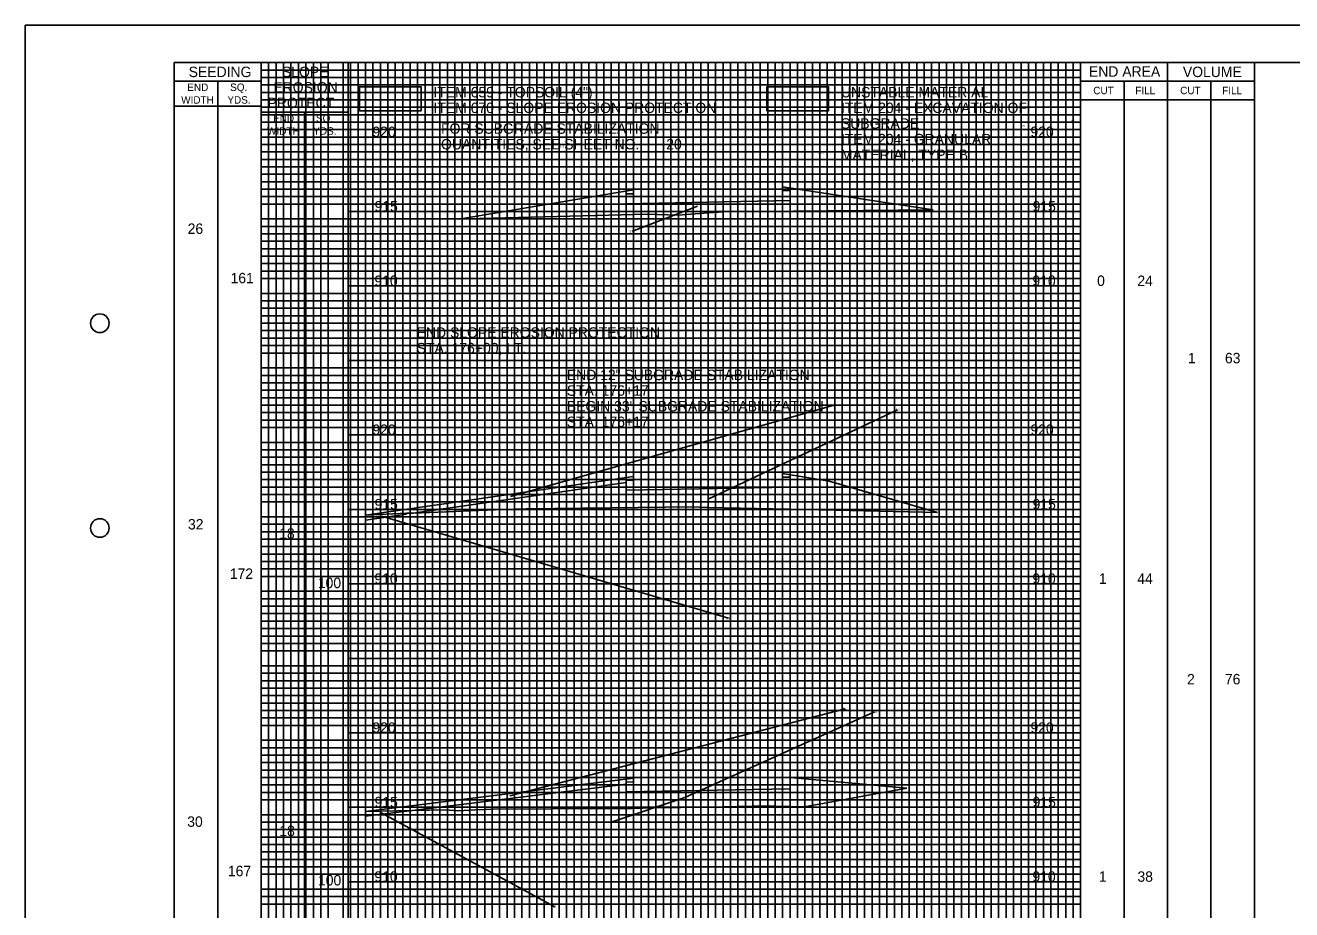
# Model space of a CAD drawing. Extents: x -73 to 160, y -2 to 1877.
# Drawn here: x -10 to 75, y 738.1 to 797.5 of the extents above; entities that cross this region are included whole.
import ezdxf

# ---------------------------------------------------------------- set-up
doc = ezdxf.new("R2010")
doc.units = 0
for name, color, linetype in [('DR_P_Flood_Boundary', 7, 'Continuous'), ('GK_Cells', 7, 'Continuous'), ('PV_P_Drive', 7, 'Continuous'), ('PV_P_EOP', 7, 'Continuous'), ('RD_X_Fence', 7, 'Continuous'), ('TX_X_5', 7, 'Continuous'), ('UT_P_Water_Cells', 7, 'Continuous'), ('XS_P_Pavt_Surface', 7, 'Continuous'), ('XS_P_Special_Benching', 7, 'Continuous'), ('XS_X_Ground_Line', 7, 'Continuous')]:
    doc.layers.add(name, color=color, linetype=linetype)

msp = doc.modelspace()

# ---------------------------------------------------------------- linework, layer by layer
at = {"layer": 'DR_P_Flood_Boundary'}
for p, q in [((15.832, 690), (15.832, 795)), ((20.832, 690), (20.832, 795)), ((25.832, 690), (25.832, 795)), ((30.832, 690), (30.832, 795)), ((35.832, 690), (35.832, 795)), ((40.832, 690), (40.832, 795)), ((45.832, 690), (45.832, 795)), ((50.832, 690), (50.832, 795)), ((55.832, 690), (55.832, 795)), ((5.832, 790), (60.832, 790)), ((11.665, 785), (60.832, 785)), ((11.665, 780), (60.832, 780)), ((11.665, 775), (60.832, 775)), ((11.665, 770), (60.832, 770)), ((11.665, 765), (60.832, 765)), ((11.665, 760), (60.832, 760)), ((11.665, 755), (60.832, 755)), ((11.665, 750), (60.832, 750)), ((11.665, 745), (60.832, 745)), ((11.665, 740), (60.832, 740))]:
    msp.add_line(p, q, dxfattribs=at)
at = {"layer": 'GK_Cells'}
msp.add_lwpolyline([(0, 795), (157.5, 795), (157.5, 690), (0, 690)], close=True, dxfattribs=at)
for centre in [(-5, 777.5), (-5, 763.75)]:
    msp.add_circle(centre, 0.625, dxfattribs=at)
at = {"layer": 'PV_P_Drive'}
msp.add_lwpolyline([(12.427, 793.375), (16.568, 793.375), (16.568, 791.76), (12.427, 791.76)], close=True, dxfattribs=at)
msp.add_lwpolyline([(12.427, 791.76), (16.568, 791.76), (16.568, 793.375), (12.427, 793.375), (12.427, 791.76)], dxfattribs=at)
at = {"layer": 'PV_P_EOP'}
msp.add_lwpolyline([(39.777, 793.375), (43.917, 793.375), (43.917, 791.76), (39.777, 791.76)], close=True, dxfattribs=at)
msp.add_lwpolyline([(39.777, 791.76), (43.917, 791.76), (43.917, 793.375), (39.777, 793.375), (39.777, 791.76)], dxfattribs=at)
at = {"layer": 'RD_X_Fence'}
for p, q in [((30.832, 786.447), (19.095, 784.49)), ((50.943, 785.106), (40.832, 786.647)), ((40.832, 786.397), (41.332, 786.407)), ((41.332, 786.407), (41.332, 785.74)), ((30.332, 786.187), (30.832, 786.197)), ((30.332, 785.52), (30.332, 786.187)), ((41.332, 785.74), (30.332, 785.52)), ((35.107, 785.349), (30.759, 783.677)), ((22.573, 765.857), (44.2, 771.986)), ((35.873, 765.714), (48.535, 771.688)), ((30.832, 767.21), (12.833, 764.607)), ((30.332, 766.808), (16.041, 764.741)), ((16.041, 764.741), (30.332, 766.808)), ((30.332, 766.95), (30.832, 766.96)), ((30.332, 766.808), (30.332, 766.95)), ((30.332, 766.283), (30.332, 766.808)), ((30.832, 767.106), (30.832, 767.21)), ((30.832, 766.96), (30.832, 767.106)), ((43.956, 766.889), (40.832, 767.41)), ((40.832, 767.16), (41.332, 767.17)), ((41.332, 767.17), (41.332, 766.503)), ((51.237, 764.788), (43.956, 766.889)), ((41.332, 766.503), (30.332, 766.283)), ((35.832, 765.135), (42.332, 764.988)), ((15.585, 764.742), (12.833, 764.607)), ((12.833, 764.277), (15.595, 764.676)), ((12.833, 764.607), (12.833, 764.277)), ((13.906, 764.546), (37.188, 757.697)), ((42.332, 764.988), (51.237, 764.788)), ((22.514, 745.765), (45.027, 751.613)), ((34.266, 745.651), (46.992, 751.4)), ((30.832, 746.955), (12.833, 744.724)), ((30.332, 746.563), (15.982, 744.784)), ((15.982, 744.784), (30.332, 746.563)), ((30.332, 746.563), (30.332, 746.695)), ((30.332, 746.028), (30.332, 746.563)), ((30.832, 746.851), (30.832, 746.955)), ((30.832, 746.709), (30.832, 746.851)), ((41.332, 746.915), (41.332, 746.248)), ((49.173, 746.293), (41.341, 747.005)), ((34.397, 745.692), (29.453, 744.046)), ((41.332, 746.248), (30.332, 746.028)), ((42.303, 745.034), (49.173, 746.293)), ((12.833, 744.394), (15.982, 744.784)), ((15.982, 744.784), (12.833, 744.724)), ((12.833, 744.724), (15.982, 744.784)), ((12.833, 744.724), (12.833, 744.394)), ((13.882, 744.634), (25.532, 738.324)), ((29.332, 744.919), (30.687, 744.926)), ((30.687, 744.926), (32.177, 744.953)), ((32.177, 744.953), (35.833, 745.018)), ((35.833, 745.018), (38.881, 745.073)), ((38.881, 745.073), (40.306, 745.085)), ((40.306, 745.085), (42.303, 745.034))]:
    msp.add_line(p, q, dxfattribs=at)
for points in [[(30.832, 786.197), (30.832, 786.342), (30.832, 786.447)], [(40.832, 786.647), (40.832, 786.542), (40.832, 786.397)], [(19.095, 784.49), (20.479, 784.529), (31.739, 784.832), (33.798, 784.764), (35.832, 784.912), (36.891, 784.989), (50.943, 785.106)], [(40.832, 767.41), (40.832, 767.306), (40.832, 767.16)], [(16.041, 764.741), (22.09, 764.99), (23.611, 765.028), (29.332, 765.108), (32.952, 765.159), (34.328, 765.171)], [(34.328, 765.171), (35.254, 765.149), (35.832, 765.135)], [(12.833, 764.607), (15.585, 764.742), (16.041, 764.741)], [(15.595, 764.676), (15.585, 764.742)], [(30.332, 746.695), (30.832, 746.709), (30.832, 746.709)], [(41.341, 747.005), (41.332, 746.915)], [(15.982, 744.784), (18.202, 744.827), (19.045, 744.766), (20.205, 744.823), (21.369, 744.877), (29.332, 744.919)]]:
    msp.add_lwpolyline(points, dxfattribs=at)
at = {"layer": 'TX_X_5'}
msp.add_lwpolyline([(-10, 687.5), (160, 687.5), (160, 797.5), (-10, 797.5)], close=True, dxfattribs=at)
at = {"layer": 'UT_P_Water_Cells'}
for p, q in [((6.332, 690), (6.332, 795)), ((6.832, 690), (6.832, 795)), ((7.332, 690), (7.332, 795)), ((7.832, 690), (7.832, 795)), ((8.332, 690), (8.332, 795)), ((8.832, 690), (8.832, 795)), ((9.332, 690), (9.332, 795)), ((9.832, 690), (9.832, 795)), ((10.332, 690), (10.332, 795)), ((11.332, 690), (11.332, 795)), ((11.832, 690), (11.832, 795)), ((12.332, 690), (12.332, 795)), ((12.832, 690), (12.832, 795)), ((13.332, 690), (13.332, 795)), ((13.832, 690), (13.832, 795)), ((14.332, 690), (14.332, 795)), ((14.832, 690), (14.832, 795)), ((15.332, 690), (15.332, 795)), ((16.332, 690), (16.332, 795)), ((16.832, 690), (16.832, 795)), ((17.332, 690), (17.332, 795)), ((17.832, 690), (17.832, 795)), ((18.332, 690), (18.332, 795)), ((18.832, 690), (18.832, 795)), ((19.332, 690), (19.332, 795)), ((19.832, 690), (19.832, 795)), ((20.332, 690), (20.332, 795)), ((21.332, 690), (21.332, 795)), ((21.832, 690), (21.832, 795)), ((22.332, 690), (22.332, 795)), ((22.832, 690), (22.832, 795)), ((23.332, 690), (23.332, 795)), ((23.832, 690), (23.832, 795)), ((24.332, 690), (24.332, 795)), ((24.832, 690), (24.832, 795)), ((25.332, 690), (25.332, 795)), ((26.332, 690), (26.332, 795)), ((26.832, 690), (26.832, 795)), ((27.332, 690), (27.332, 795)), ((27.832, 690), (27.832, 795)), ((28.332, 690), (28.332, 795)), ((28.832, 690), (28.832, 795)), ((29.332, 690), (29.332, 795)), ((29.832, 690), (29.832, 795)), ((30.332, 690), (30.332, 795)), ((31.332, 690), (31.332, 795)), ((31.832, 690), (31.832, 795)), ((32.332, 690), (32.332, 795)), ((32.832, 690), (32.832, 795)), ((33.332, 690), (33.332, 795)), ((33.832, 690), (33.832, 795)), ((34.332, 690), (34.332, 795)), ((34.832, 690), (34.832, 795)), ((35.332, 690), (35.332, 795)), ((36.332, 690), (36.332, 795)), ((36.832, 690), (36.832, 795)), ((37.332, 690), (37.332, 795)), ((37.832, 690), (37.832, 795)), ((38.332, 690), (38.332, 795)), ((38.832, 690), (38.832, 795)), ((39.332, 690), (39.332, 795)), ((39.832, 690), (39.832, 795)), ((40.332, 690), (40.332, 795)), ((41.332, 690), (41.332, 795)), ((41.832, 690), (41.832, 795)), ((42.332, 690), (42.332, 795)), ((42.832, 690), (42.832, 795)), ((43.332, 690), (43.332, 795)), ((43.832, 690), (43.832, 795)), ((44.332, 690), (44.332, 795)), ((44.832, 690), (44.832, 795)), ((45.332, 690), (45.332, 795)), ((46.332, 690), (46.332, 795)), ((46.832, 690), (46.832, 795)), ((47.332, 690), (47.332, 795)), ((47.832, 690), (47.832, 795)), ((48.332, 690), (48.332, 795)), ((48.832, 690), (48.832, 795)), ((49.332, 690), (49.332, 795)), ((49.832, 690), (49.832, 795)), ((50.332, 690), (50.332, 795)), ((51.332, 690), (51.332, 795)), ((51.832, 690), (51.832, 795)), ((52.332, 690), (52.332, 795)), ((52.832, 690), (52.832, 795)), ((53.332, 690), (53.332, 795)), ((53.832, 690), (53.832, 795)), ((54.332, 690), (54.332, 795)), ((54.832, 690), (54.832, 795)), ((55.332, 690), (55.332, 795)), ((56.332, 690), (56.332, 795)), ((56.832, 690), (56.832, 795)), ((57.332, 690), (57.332, 795)), ((57.832, 690), (57.832, 795)), ((58.332, 690), (58.332, 795)), ((58.832, 690), (58.832, 795)), ((59.332, 690), (59.332, 795)), ((59.832, 690), (59.832, 795)), ((60.332, 690), (60.332, 795)), ((5.832, 794.5), (60.832, 794.5)), ((5.832, 794), (60.832, 794)), ((5.832, 793.5), (60.832, 793.5)), ((5.832, 793), (60.832, 793)), ((5.832, 792.5), (60.832, 792.5)), ((5.832, 792), (60.832, 792)), ((5.832, 791.5), (60.832, 791.5)), ((5.832, 791), (60.832, 791)), ((5.832, 790.5), (60.832, 790.5)), ((5.832, 789.5), (60.832, 789.5)), ((5.832, 789), (60.832, 789)), ((5.832, 788.5), (60.832, 788.5)), ((5.832, 788), (60.832, 788)), ((5.832, 787.5), (60.832, 787.5)), ((5.832, 787), (60.832, 787)), ((5.832, 786.5), (60.832, 786.5)), ((5.832, 786), (60.832, 786)), ((5.832, 785.5), (60.832, 785.5)), ((5.832, 784.5), (60.832, 784.5)), ((5.832, 784), (60.832, 784)), ((5.832, 783.5), (60.832, 783.5)), ((5.832, 783), (60.832, 783)), ((5.832, 782.5), (60.832, 782.5)), ((5.832, 782), (60.832, 782)), ((5.832, 781.5), (60.832, 781.5)), ((5.832, 781), (60.832, 781)), ((5.832, 780.5), (60.832, 780.5)), ((5.832, 779.5), (60.832, 779.5)), ((5.832, 779), (60.832, 779)), ((5.832, 778.5), (60.832, 778.5)), ((5.832, 778), (60.832, 778)), ((5.832, 777.5), (60.832, 777.5)), ((5.832, 777), (60.832, 777)), ((5.832, 776.5), (60.832, 776.5)), ((5.832, 776), (60.832, 776)), ((5.832, 775.5), (60.832, 775.5)), ((5.832, 774.5), (60.832, 774.5)), ((5.832, 774), (60.832, 774)), ((5.832, 773.5), (60.832, 773.5)), ((5.832, 773), (60.832, 773)), ((5.832, 772.5), (60.832, 772.5)), ((5.832, 772), (60.832, 772)), ((5.832, 771.5), (60.832, 771.5)), ((5.832, 771), (60.832, 771)), ((5.832, 770.5), (60.832, 770.5)), ((5.832, 769.5), (60.832, 769.5)), ((5.832, 769), (60.832, 769)), ((5.832, 768.5), (60.832, 768.5)), ((5.832, 768), (60.832, 768)), ((5.832, 767.5), (60.832, 767.5)), ((5.832, 767), (60.832, 767)), ((5.832, 766.5), (60.832, 766.5)), ((5.832, 766), (60.832, 766)), ((5.832, 765.5), (60.832, 765.5)), ((5.832, 764.5), (60.832, 764.5)), ((5.832, 764), (60.832, 764)), ((5.832, 763.5), (60.832, 763.5)), ((5.832, 763), (60.832, 763)), ((5.832, 762.5), (60.832, 762.5)), ((5.832, 762), (60.832, 762)), ((5.832, 761.5), (60.832, 761.5)), ((5.832, 761), (60.832, 761)), ((5.832, 760.5), (60.832, 760.5)), ((5.832, 759.5), (60.832, 759.5)), ((5.832, 759), (60.832, 759)), ((5.832, 758.5), (60.832, 758.5)), ((5.832, 758), (60.832, 758)), ((5.832, 757.5), (60.832, 757.5)), ((5.832, 757), (60.832, 757)), ((5.832, 756.5), (60.832, 756.5)), ((5.832, 756), (60.832, 756)), ((5.832, 755.5), (60.832, 755.5)), ((5.832, 754.5), (60.832, 754.5)), ((5.832, 754), (60.832, 754)), ((5.832, 753.5), (60.832, 753.5)), ((5.832, 753), (60.832, 753)), ((5.832, 752.5), (60.832, 752.5)), ((5.832, 752), (60.832, 752)), ((5.832, 751.5), (60.832, 751.5)), ((5.832, 751), (60.832, 751)), ((5.832, 750.5), (60.832, 750.5)), ((5.832, 749.5), (60.832, 749.5)), ((5.832, 749), (60.832, 749)), ((5.832, 748.5), (60.832, 748.5)), ((5.832, 748), (60.832, 748)), ((5.832, 747.5), (60.832, 747.5)), ((5.832, 747), (60.832, 747)), ((5.832, 746.5), (60.832, 746.5)), ((5.832, 746), (60.832, 746)), ((5.832, 745.5), (60.832, 745.5)), ((5.832, 744.5), (60.832, 744.5)), ((5.832, 744), (60.832, 744)), ((5.832, 743.5), (60.832, 743.5)), ((5.832, 743), (60.832, 743)), ((5.832, 742.5), (60.832, 742.5)), ((5.832, 742), (60.832, 742)), ((5.832, 741.5), (60.832, 741.5)), ((5.832, 741), (60.832, 741)), ((5.832, 740.5), (60.832, 740.5)), ((5.832, 739.5), (60.832, 739.5)), ((5.832, 739), (60.832, 739)), ((5.832, 738.5), (60.832, 738.5))]:
    msp.add_line(p, q, dxfattribs=at)
at = {"layer": 'XS_X_Ground_Line'}
for p, q in [((5.832, 690), (5.832, 795)), ((5.832, 690), (5.832, 795)), ((11.665, 690), (11.665, 795)), ((60.832, 690), (60.832, 795)), ((66.667, 690), (66.667, 795)), ((72.5, 690), (72.5, 795)), ((5.832, 793.75), (0, 793.75)), ((2.916, 690), (2.916, 793.75)), ((60.832, 793.75), (72.5, 793.75)), ((63.75, 690), (63.75, 793.75)), ((69.583, 690), (69.583, 793.75)), ((60.832, 792.5), (72.5, 792.5)), ((5.832, 792.083), (0, 792.083)), ((11.665, 791.667), (5.832, 791.667)), ((8.749, 690), (8.749, 791.667)), ((11.665, 790), (5.832, 790))]:
    msp.add_line(p, q, dxfattribs=at)

# ---------------------------------------------------------------- texts
at = {"layer": 'RD_X_Fence'}
for s, p in [('2.5', (56.819, 790.675)), ('6.0', (60.181, 791.014)), ('11.9', (25.78, 789.29)), ('10.2', (43.222, 788.91)), ('24.4', (30.553, 783.607)), ('5.3', (44.04, 771.916)), ('38.2', (48.315, 771.618)), ('0.5', (37.022, 757.627)), ('5.4', (44.869, 751.543)), ('32.3', (46.772, 751.33)), ('32.7', (29.247, 743.976)), ('0.5', (25.366, 738.254))]:
    msp.add_text(s, height=0.14, dxfattribs=at).set_placement(p)
at = {"layer": 'XS_P_Pavt_Surface'}
for s, p in [('920', (13.298, 790)), ('920', (57.465, 790)), ('915', (13.441, 785)), ('915', (57.609, 785)), ('26', (0.896, 783.497)), ('161', (3.776, 780.18)), ('910', (13.43, 780)), ('910', (57.598, 780)), ('0', (61.941, 780)), ('24', (64.642, 780)), ('END SLOPE EROSION PROTECTION', (16.271, 776.526)), ('STA. 176+00, LT.', (16.271, 775.476)), ('1', (68.04, 774.81)), ('63', (70.521, 774.81)), ('END 12" SUBGRADE STABILIZATION', (26.347, 773.679)), ('STA. 176+17', (26.347, 772.629)), ('BEGIN 33" SUBGRADE STABILIZATION', (26.347, 771.579)), ('STA. 176+17', (26.347, 770.529)), ('920', (13.298, 770)), ('920', (57.465, 770)), ('915', (13.441, 765)), ('915', (57.609, 765)), ('32', (0.918, 763.651)), ('18', (7.038, 763.031)), ('172', (3.724, 760.334)), ('100', (9.634, 759.715)), ('910', (13.43, 760)), ('910', (57.598, 760)), ('1', (62.057, 760)), ('44', (64.634, 760)), ('2', (67.977, 753.254)), ('76', (70.518, 753.254)), ('920', (13.298, 750)), ('920', (57.465, 750)), ('915', (13.441, 745)), ('915', (57.609, 745)), ('30', (0.866, 743.688)), ('18', (7.049, 743.068)), ('167', (3.597, 740.371)), ('100', (9.645, 739.752)), ('910', (13.43, 740)), ('910', (57.598, 740)), ('1', (62.057, 740)), ('38', (64.648, 740))]:
    msp.add_text(s, height=0.7, dxfattribs=at).set_placement(p)
at = {"layer": 'XS_P_Special_Benching'}
for s, p in [('ITEM 659 - TOPSOIL (4")', (17.396, 792.661)), ('UNSTABLE MATERIAL', (44.745, 792.661)), ('ITEM 670 - SLOPE EROSION PROTECTION', (17.396, 791.611)), ('ITEM 204 - EXCAVATION OF', (44.745, 791.611)), ('FOR SUBGRADE STABILIZATION', (17.903, 790.22)), ('SUBGRADE', (44.745, 790.561)), ('QUANTITIES, SEE SHEET NO.', (17.903, 789.17)), ('20', (33.021, 789.17)), ('ITEM 204 - GRANULAR', (44.745, 789.511)), ('MATERIAL, TYPE B', (44.745, 788.461))]:
    msp.add_text(s, height=0.7, dxfattribs=at).set_placement(p)
at = {"layer": 'XS_X_Ground_Line'}
for s, height, p in [('SEEDING', 0.7, (0.964, 794.025)), ('SLOPE', 0.7, (7.228, 794.025)), ('END AREA', 0.7, (61.394, 794.047)), ('VOLUME', 0.7, (67.698, 794.025)), ('END', 0.5, (0.87, 793.092)), ('SQ.', 0.5, (3.748, 793.092)), ('EROSION', 0.7, (6.649, 792.983)), ('CUT', 0.5, (61.683, 792.875)), ('FILL', 0.5, (64.502, 792.875)), ('CUT', 0.5, (67.517, 792.875)), ('FILL', 0.5, (70.335, 792.875)), ('WIDTH', 0.5, (0.462, 792.242)), ('YDS.', 0.5, (3.563, 792.242)), ('PROTECT.', 0.7, (6.26, 791.942)), ('END', 0.5, (6.631, 791.008)), ('SQ.', 0.5, (9.51, 791.008)), ('WIDTH', 0.5, (6.224, 790.158)), ('YDS.', 0.5, (9.325, 790.158))]:
    msp.add_text(s, height=height, dxfattribs=at).set_placement(p)

doc.saveas('drawing.dxf')
